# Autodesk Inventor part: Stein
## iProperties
Author: Jürgen Rüther
Shininess: 20.0
Angle Display Precision: 2
Document Length Units: 11269
Document Angle Units: 11283
Document Time Units: 11279
Document Mass Units: 11290
Document Length Units Precision: 3
Document Angle Units Precision: 2
Compacted: False
PropertySet Name: _Private Model Information
Created: 2002-03
Part Number: Stein
Material: Standard
Document SubType Name: Modellieren
Designer: Jürgen Rüther
Control State: 0
Master: False
Checked Out: False
PropertySet Name: Design Tracking Control
Density: 0.0
Volumn: 0.0
Area: 0.0
PropertySet Name: Model Information
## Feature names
1. Extrusion1
2. Fase1 [Chamfer]
3. Extrusion2
4. Extrusion3
5. Extrusion4
6. Extrusion5
7. Extrusion6
